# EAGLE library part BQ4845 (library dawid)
bq4846 Real Time Clock
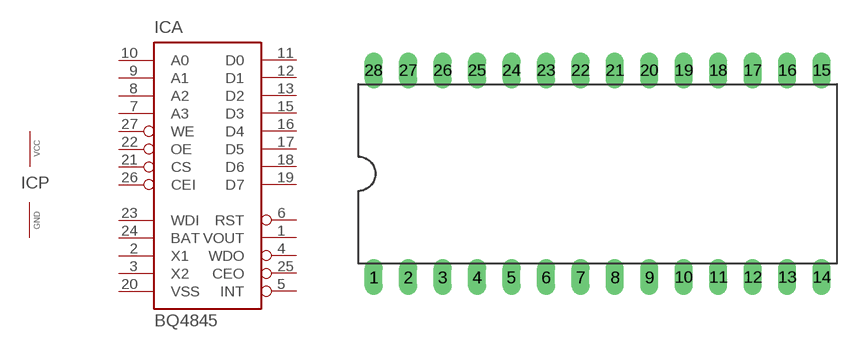
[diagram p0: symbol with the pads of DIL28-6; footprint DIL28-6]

Designator prefix IC; gates A=BQ4845 P=PWRN

## BQ4845DIL28-6  [DIL28-6]
1  A:VOUT  out
2  A:X1  in
3  A:X2  in
4  A:WDO  out
5  A:INT  out
6  A:RST  out
7  A:A3  in
8  A:A2  in
9  A:A1  in
10  A:A0  in
11  A:D0
12  A:D1
13  A:D2
14  P:GND  pwr
15  A:D3
16  A:D4
17  A:D5
18  A:D6
19  A:D7
20  A:VSS  pwr
21  A:CS  in
22  A:OE  in
23  A:WDI  in
24  A:BAT  pwr
25  A:CEO  out
26  A:CEI  in
27  A:WE  in
28  P:VCC  pwr

## Footprint DIL28-6 (pad centres in mm)
drill 0.813 long: 1 -16.51,-7.62; 2 -13.97,-7.62; 3 -11.43,-7.62; 4 -8.89,-7.62; 5 -6.35,-7.62; 6 -3.81,-7.62; 7 -1.27,-7.62; 8 1.27,-7.62; 9 3.81,-7.62; 10 6.35,-7.62; 11 8.89,-7.62; 12 11.43,-7.62; 13 13.97,-7.62; 14 16.51,-7.62; 15 16.51,7.62; 16 13.97,7.62; 17 11.43,7.62; 18 8.89,7.62; 19 6.35,7.62; 20 3.81,7.62; 21 1.27,7.62; 22 -1.27,7.62; 23 -3.81,7.62; 24 -6.35,7.62; 25 -8.89,7.62; 26 -11.43,7.62; 27 -13.97,7.62; 28 -16.51,7.62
